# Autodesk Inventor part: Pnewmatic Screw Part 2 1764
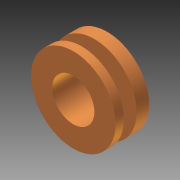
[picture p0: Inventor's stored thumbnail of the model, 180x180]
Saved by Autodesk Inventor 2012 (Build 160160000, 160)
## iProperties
Created: 2010-02
Part Number: Pnewmatic Screw Part 2 1764
Document SubType Name: Modeling
Designer: clee1
Density: 1 g/cm^3
Material: Default
Author: clee1
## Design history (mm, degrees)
sketch "Sketch1"
  geometry: C1 r 6.35 at (0, 0); 1 further point
  constraints: 1 centre point, 1 coincident
  dimensions: "d0" = 12.7 diameter of C1
extrude "Extrusion1" new body sketch "Sketch1" distance "d1" = 1.905; taper "d2" = 0 deg
sketch "Sketch2"
  geometry: C1 r 6.35 at (0, 0) reference; C2 r 3.493 at (0, 0)
  constraints: 1 centre point, 1 coincident
  dimensions: "d3" = 6.985 diameter of C2
extrude "Extrusion2" join sketch "Sketch2" distance "d4" = 1.905; taper "d5" = 0 deg
sketch "Sketch3"
  geometry: C1 r 3.493 at (0, 0) reference; C2 r 6.35 at (0, 0) reference; C3 r 6.35 at (0, 0)
  constraints: 1 centre point, 1 coincident, 1 concentric
extrude "Extrusion3" join sketch "Sketch3" distance "d6" = 1.27; taper "d7" = 0 deg
sketch "Sketch4"
  geometry: C1 r 6.35 at (0, 0) reference; C2 r 3.175 at (0, 0)
  constraints: 1 centre point, 1 coincident
  dimensions: "d8" = 6.35 diameter of C2
extrude "Extrusion4" cut sketch "Sketch4" stored distance "d9" = 1.27; taper "d10" = 0 deg
body "Solid1"
node "Projected Loop1"
